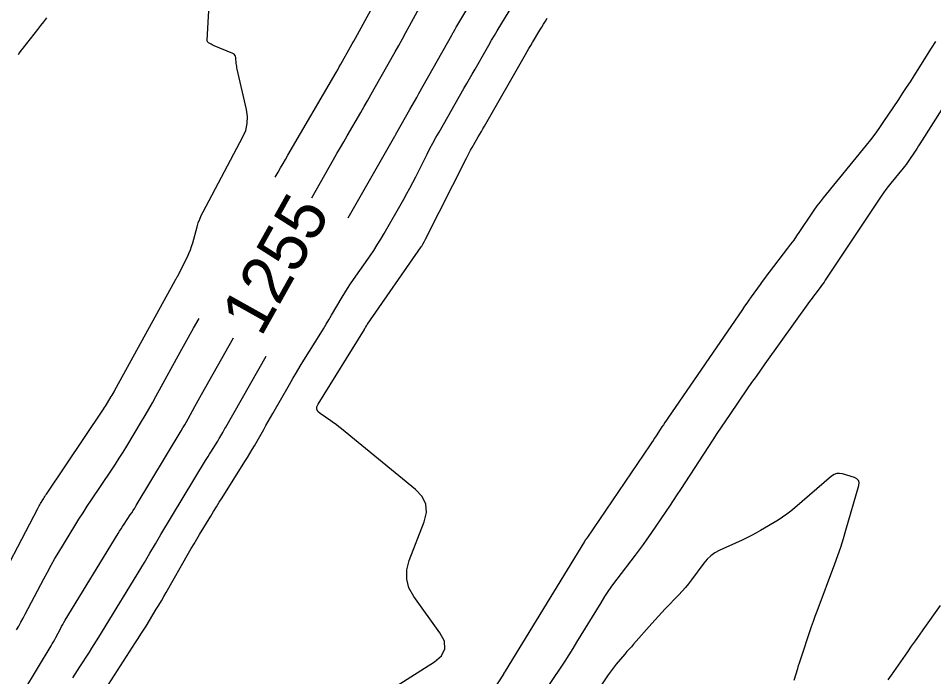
# Model space of a CAD drawing. Extents: x 658976 to 668726, y 639543 to 647196.
# Drawn here: x 661779.9 to 661893.9, y 641412.7 to 641494.7 of the extents above; entities that cross this region are included whole.
import ezdxf

# ---------------------------------------------------------------- set-up
doc = ezdxf.new("R2010")
doc.units = 0
for name, color, linetype in [('Ex_Contour Labels', 7, 'Continuous'), ('Ex_Major Contours', 7, 'Continuous'), ('Ex_Minor Contours', 7, 'Continuous')]:
    doc.layers.add(name, color=color, linetype=linetype)

msp = doc.modelspace()

# ---------------------------------------------------------------- linework, layer by layer
at = {"layer": 'Ex_Major Contours'}
for points in [[(661816.47, 641472.36), (661819.18, 641477.14), (661819.6, 641477.87), (661820.02, 641478.61), (661820.44, 641479.34), (661820.87, 641480.07), (661822.57, 641482.99), (661822.99, 641483.72), (661823.41, 641484.45), (661823.83, 641485.18), (661824.24, 641485.92), (661826.85, 641490.55), (661827.3, 641491.35), (661827.74, 641492.16), (661828.19, 641492.96), (661828.63, 641493.77), (661830.39, 641496.99)], [(661780.62, 641410.89), (661783.99, 641416.52), (661784.15, 641416.78), (661784.3, 641417.04), (661784.45, 641417.31), (661784.59, 641417.58), (661785.15, 641418.66), (661785.3, 641418.93), (661785.44, 641419.19), (661785.6, 641419.45), (661785.75, 641419.72), (661792.34, 641430.53), (661792.52, 641430.83), (661792.71, 641431.12), (661792.9, 641431.41), (661793.09, 641431.69), (661793.85, 641432.84), (661794.04, 641433.12), (661794.23, 641433.41), (661794.41, 641433.7), (661794.59, 641434), (661800.2, 641443.31), (661800.42, 641443.68), (661800.64, 641444.06), (661800.85, 641444.44), (661801.06, 641444.82), (661801.9, 641446.34), (661802.11, 641446.72), (661802.32, 641447.1), (661802.53, 641447.48), (661802.74, 641447.86), (661806.7, 641454.91)]]:
    msp.add_lwpolyline(points, dxfattribs=at)
at = {"layer": 'Ex_Minor Contours'}
for points in [[(661820.98, 641469.84), (661826.8, 641480.02), (661826.82, 641480.05), (661826.84, 641480.09), (661826.86, 641480.13), (661826.88, 641480.17), (661826.96, 641480.33), (661826.98, 641480.37), (661827, 641480.4), (661827.02, 641480.44), (661827.04, 641480.48), (661828.69, 641483.36), (661828.97, 641483.86), (661829.25, 641484.35), (661829.53, 641484.84), (661829.81, 641485.34), (661833.89, 641492.61), (661833.95, 641492.7), (661834, 641492.79), (661834.05, 641492.89), (661834.1, 641492.98), (661834.3, 641493.35), (661834.35, 641493.44), (661834.41, 641493.53), (661834.46, 641493.62), (661834.51, 641493.72), (661840.84, 641504.31)], [(661811.91, 641474.91), (661812.28, 641475.57), (661812.58, 641476.09), (661812.88, 641476.62), (661813.18, 641477.14), (661813.49, 641477.67), (661819.48, 641487.95), (661819.69, 641488.31), (661819.89, 641488.66), (661820.09, 641489.02), (661820.29, 641489.38), (661821.09, 641490.8), (661821.29, 641491.16), (661821.49, 641491.52), (661821.69, 641491.88), (661821.89, 641492.23), (661827.89, 641503.22)], [(661788.92, 641408.24), (661794.52, 641416.94), (661794.84, 641417.45), (661795.17, 641417.97), (661795.49, 641418.48), (661795.82, 641419), (661797.09, 641421.09), (661797.41, 641421.61), (661797.73, 641422.13), (661798.03, 641422.66), (661798.34, 641423.19), (661801.12, 641428.08), (661801.46, 641428.66), (661801.8, 641429.24), (661802.14, 641429.82), (661802.48, 641430.4), (661803.87, 641432.7), (661804.22, 641433.27), (661804.58, 641433.85), (661804.93, 641434.42), (661805.29, 641434.99), (661808.14, 641439.5), (661808.45, 641439.99), (661808.75, 641440.48), (661809.04, 641440.98), (661809.33, 641441.47), (661810.48, 641443.47), (661810.76, 641443.97), (661811.05, 641444.47), (661811.33, 641444.97), (661811.62, 641445.47), (661813.68, 641449.09), (661814.12, 641449.85), (661814.57, 641450.61), (661815.02, 641451.36), (661815.48, 641452.11), (661817.57, 641455.49), (661817.91, 641456.04), (661818.25, 641456.6), (661818.58, 641457.16), (661818.92, 641457.72), (661820.25, 641459.96), (661820.58, 641460.52), (661820.93, 641461.07), (661821.29, 641461.62), (661821.66, 641462.16), (661823.72, 641465.12), (661824.17, 641465.8), (661824.62, 641466.49), (661825.05, 641467.19), (661825.46, 641467.89), (661827.92, 641472.19), (661828.31, 641472.88), (661828.68, 641473.57), (661829.05, 641474.26), (661829.41, 641474.97), (661830.82, 641477.78), (661831.18, 641478.48), (661831.55, 641479.18), (661831.93, 641479.87), (661832.31, 641480.55), (661835.41, 641485.98), (661835.76, 641486.58), (661836.1, 641487.18), (661836.45, 641487.78), (661836.79, 641488.38), (661838.17, 641490.78), (661838.51, 641491.38), (661838.86, 641491.98), (661839.21, 641492.58), (661839.57, 641493.17), (661843, 641498.86)], [(661776.38, 641422.27), (661782.34, 641433.66), (661782.42, 641433.82), (661782.5, 641433.97), (661782.59, 641434.12), (661782.68, 641434.26), (661783.04, 641434.85), (661783.13, 641435), (661783.22, 641435.15), (661783.31, 641435.29), (661783.41, 641435.43), (661790.53, 641446.02), (661790.66, 641446.21), (661790.78, 641446.41), (661790.9, 641446.6), (661791.02, 641446.8), (661791.49, 641447.58), (661791.61, 641447.78), (661791.73, 641447.98), (661791.84, 641448.18), (661791.95, 641448.38), (661799.46, 641462.07), (661799.48, 641462.12), (661799.51, 641462.16), (661799.54, 641462.21), (661799.56, 641462.26), (661799.67, 641462.44), (661799.69, 641462.49), (661799.72, 641462.54), (661799.74, 641462.59), (661799.77, 641462.63), (661800.98, 641465.01), (661801.17, 641465.43), (661801.35, 641465.86), (661801.5, 641466.29), (661801.64, 641466.73), (661802.18, 641468.75), (661802.33, 641469.23), (661802.5, 641469.7), (661802.7, 641470.16), (661802.92, 641470.6), (661807.88, 641479.94), (661808.24, 641480.76), (661808.43, 641481.6), (661808.46, 641482.47), (661808.33, 641483.35), (661807.18, 641488.37), (661807.14, 641488.55), (661807.11, 641488.73), (661807.08, 641488.91), (661807.06, 641489.1), (661807.01, 641489.83), (661806.97, 641490), (661806.9, 641490.14), (661806.79, 641490.25), (661806.64, 641490.33), (661804.31, 641491.29), (661804.22, 641491.33), (661804.13, 641491.38), (661804.04, 641491.42), (661803.95, 641491.48), (661803.6, 641491.68), (661803.53, 641491.74), (661803.47, 641491.81), (661803.44, 641491.89), (661803.44, 641491.99), (661803.77, 641497.92)], [(661783.43, 641494.77), (661783.05, 641494.3), (661782.68, 641493.82), (661782.3, 641493.34), (661780.47, 641491), (661780.27, 641490.73), (661780.07, 641490.46), (661779.88, 641490.18)], [(661825.38, 641410.52), (661831.73, 641414.52), (661832.63, 641415.29), (661833.05, 641416.16), (661832.99, 641417.12), (661832.43, 641418.17), (661829.18, 641422.7), (661828.57, 641423.76), (661828.28, 641424.86), (661828.29, 641426), (661828.6, 641427.18), (661830.46, 641431.98), (661830.74, 641433.14), (661830.66, 641434.19), (661830.21, 641435.15), (661829.4, 641436.01), (661820.16, 641443.58), (661819.84, 641443.84), (661819.51, 641444.09), (661819.18, 641444.33), (661818.85, 641444.57), (661817.5, 641445.5), (661817.23, 641445.75), (661817.1, 641446.02), (661817.11, 641446.33), (661817.25, 641446.66), (661823.01, 641455.96), (661823.04, 641456.02), (661823.07, 641456.07), (661823.1, 641456.12), (661823.14, 641456.18), (661823.26, 641456.39), (661823.3, 641456.45), (661823.33, 641456.5), (661823.36, 641456.55), (661823.4, 641456.6), (661830.1, 641466.26), (661830.15, 641466.33), (661830.2, 641466.41), (661830.25, 641466.48), (661830.29, 641466.56), (661830.47, 641466.87), (661830.51, 641466.95), (661830.56, 641467.03), (661830.6, 641467.11), (661830.64, 641467.19), (661835.72, 641477.28), (661835.89, 641477.62), (661836.07, 641477.96), (661836.25, 641478.3), (661836.44, 641478.63), (661837.2, 641479.97), (661837.39, 641480.3), (661837.58, 641480.63), (661837.77, 641480.96), (661837.97, 641481.3), (661843.06, 641490.2), (661843.28, 641490.58), (661843.51, 641490.96), (661843.73, 641491.34), (661843.96, 641491.72), (661844.87, 641493.23), (661845.1, 641493.6), (661845.33, 641493.98), (661845.55, 641494.36), (661845.78, 641494.74)], [(661894.13, 641491.81), (661893.62, 641490.99), (661891.44, 641487.56), (661890.97, 641486.82), (661890.49, 641486.08), (661890.01, 641485.35), (661889.53, 641484.62), (661887.59, 641481.72), (661887.1, 641481), (661886.59, 641480.29), (661886.06, 641479.59), (661885.52, 641478.91), (661880.17, 641472.37), (661879.77, 641471.87), (661879.38, 641471.35), (661879, 641470.83), (661878.64, 641470.3), (661877.21, 641468.15), (661876.85, 641467.62), (661876.48, 641467.09), (661876.1, 641466.57), (661875.71, 641466.06), (661873.42, 641463.08), (661873.13, 641462.7), (661872.85, 641462.32), (661872.57, 641461.94), (661872.29, 641461.55), (661871.18, 641460), (661870.9, 641459.62), (661870.63, 641459.23), (661870.36, 641458.84), (661870.09, 641458.44), (661860.82, 641444.91), (661860.63, 641444.64), (661860.44, 641444.36), (661860.26, 641444.08), (661860.07, 641443.8), (661859.34, 641442.68), (661859.16, 641442.4), (661858.97, 641442.12), (661858.78, 641441.84), (661858.6, 641441.56), (661850.72, 641429.96), (661850.7, 641429.93), (661850.67, 641429.89), (661850.64, 641429.86), (661850.62, 641429.82), (661850.51, 641429.68), (661850.49, 641429.65), (661850.46, 641429.61), (661850.44, 641429.58), (661850.41, 641429.54), (661840.56, 641413.36), (661840.54, 641413.33), (661840.52, 641413.3), (661840.5, 641413.27), (661840.48, 641413.24), (661840.4, 641413.11), (661840.38, 641413.08), (661840.36, 641413.05), (661840.34, 641413.02), (661840.32, 641412.99), (661833.08, 641401.88)], [(661899.9, 641491.26), (661892.18, 641479.07), (661892.01, 641478.81), (661891.84, 641478.55), (661891.68, 641478.29), (661891.51, 641478.04), (661890.83, 641477.02), (661890.65, 641476.76), (661890.47, 641476.51), (661890.29, 641476.27), (661890.1, 641476.03), (661888.57, 641474.17), (661888.26, 641473.77), (661887.95, 641473.37), (661887.66, 641472.96), (661887.38, 641472.55), (661880.42, 641462.08), (661880.26, 641461.85), (661880.1, 641461.63), (661879.94, 641461.41), (661879.77, 641461.18), (661879.1, 641460.31), (661878.93, 641460.09), (661878.77, 641459.87), (661878.6, 641459.65), (661878.44, 641459.42), (661872.9, 641451.68), (661872.34, 641450.9), (661871.79, 641450.11), (661871.24, 641449.33), (661870.69, 641448.54), (661868.52, 641445.37), (661867.98, 641444.58), (661867.45, 641443.78), (661866.92, 641442.98), (661866.39, 641442.18), (661862.38, 641436.02), (661861.92, 641435.33), (661861.46, 641434.63), (661861, 641433.94), (661860.54, 641433.26), (661858.67, 641430.51), (661858.2, 641429.83), (661857.72, 641429.15), (661857.23, 641428.48), (661856.73, 641427.82), (661854.47, 641424.86), (661853.93, 641424.14), (661853.42, 641423.41), (661852.92, 641422.67), (661852.45, 641421.91), (661849.45, 641416.99), (661848.96, 641416.2), (661848.47, 641415.41), (661847.97, 641414.63), (661847.46, 641413.86), (661845.34, 641410.68)], [(661779.67, 641418.51), (661779.96, 641419), (661780.24, 641419.5), (661780.52, 641419.99), (661780.78, 641420.5), (661783.08, 641424.88), (661783.53, 641425.73), (661783.99, 641426.57), (661784.47, 641427.4), (661784.96, 641428.22), (661786.96, 641431.5), (661787.46, 641432.31), (661787.98, 641433.12), (661788.5, 641433.93), (661789.03, 641434.73), (661791.52, 641438.43), (661792.01, 641439.17), (661792.49, 641439.92), (661792.97, 641440.67), (661793.43, 641441.43), (661795.27, 641444.49), (661795.72, 641445.25), (661796.17, 641446.02), (661796.61, 641446.8), (661797.05, 641447.58), (661800.09, 641453.14), (661800.5, 641453.88), (661800.92, 641454.63), (661801.33, 641455.38), (661801.75, 641456.12), (661802.42, 641457.31)], [(661786.7, 641412.53), (661786.99, 641412.99), (661787.28, 641413.46), (661787.57, 641413.92), (661788.76, 641415.76), (661789.06, 641416.23), (661789.35, 641416.69), (661789.64, 641417.15), (661789.93, 641417.62), (661795.63, 641426.9), (661795.8, 641427.19), (661795.97, 641427.48), (661796.14, 641427.77), (661796.31, 641428.06), (661796.98, 641429.23), (661797.15, 641429.52), (661797.32, 641429.82), (661797.49, 641430.11), (661797.66, 641430.4), (661803.23, 641439.62), (661803.39, 641439.88), (661803.55, 641440.14), (661803.71, 641440.4), (661803.88, 641440.65), (661804.66, 641441.9), (661804.76, 641442.05), (661804.85, 641442.2), (661804.94, 641442.36), (661805.03, 641442.51), (661805.39, 641443.13), (661805.48, 641443.29), (661805.57, 641443.44), (661805.65, 641443.6), (661805.74, 641443.76), (661810.8, 641452.62)], [(661876.55, 641412.25), (661876.99, 641413.71), (661877.09, 641414.07), (661877.21, 641414.43), (661877.32, 641414.8), (661877.44, 641415.16), (661878.49, 641418.31), (661878.7, 641418.95), (661878.93, 641419.6), (661879.16, 641420.24), (661879.39, 641420.87), (661881.61, 641426.77), (661881.99, 641427.8), (661882.34, 641428.84), (661882.67, 641429.89), (661882.99, 641430.94), (661884.58, 641436.53), (661884.63, 641436.88), (661884.56, 641437.15), (661884.36, 641437.36), (661884.05, 641437.51), (661882.55, 641437.95), (661882.18, 641438.02), (661881.84, 641437.99), (661881.51, 641437.87), (661881.2, 641437.66), (661876.64, 641433.72), (661876.14, 641433.31), (661875.63, 641432.92), (661875.1, 641432.56), (661874.56, 641432.21), (661872.34, 641430.9), (661871.78, 641430.58), (661871.22, 641430.27), (661870.64, 641429.98), (661870.06, 641429.71), (661867.21, 641428.41), (661866.65, 641428.12), (661866.15, 641427.76), (661865.7, 641427.34), (661865.3, 641426.85), (661863.77, 641424.76), (661863.4, 641424.27), (661863.02, 641423.8), (661862.61, 641423.33), (661862.19, 641422.89), (661860.48, 641421.13), (661860.05, 641420.69), (661859.63, 641420.24), (661859.22, 641419.79), (661858.81, 641419.33), (661856.53, 641416.74), (661856.26, 641416.43), (661855.99, 641416.12), (661855.72, 641415.81), (661855.45, 641415.49), (661854.38, 641414.24), (661854.12, 641413.92), (661853.87, 641413.59), (661853.63, 641413.26), (661853.39, 641412.92), (661848.45, 641405.5)], [(661888.23, 641412.28), (661888.67, 641412.9), (661890.68, 641415.79), (661891.16, 641416.48), (661891.64, 641417.17), (661892.13, 641417.85), (661892.61, 641418.54), (661894.76, 641421.58)]]:
    msp.add_lwpolyline(points, dxfattribs=at)

# ---------------------------------------------------------------- texts
at = {"layer": 'Ex_Contour Labels'}
msp.add_text('1255', height=6, rotation=60.7686, dxfattribs=at).set_placement((661810.14, 641454.9))

doc.saveas('drawing.dxf')
